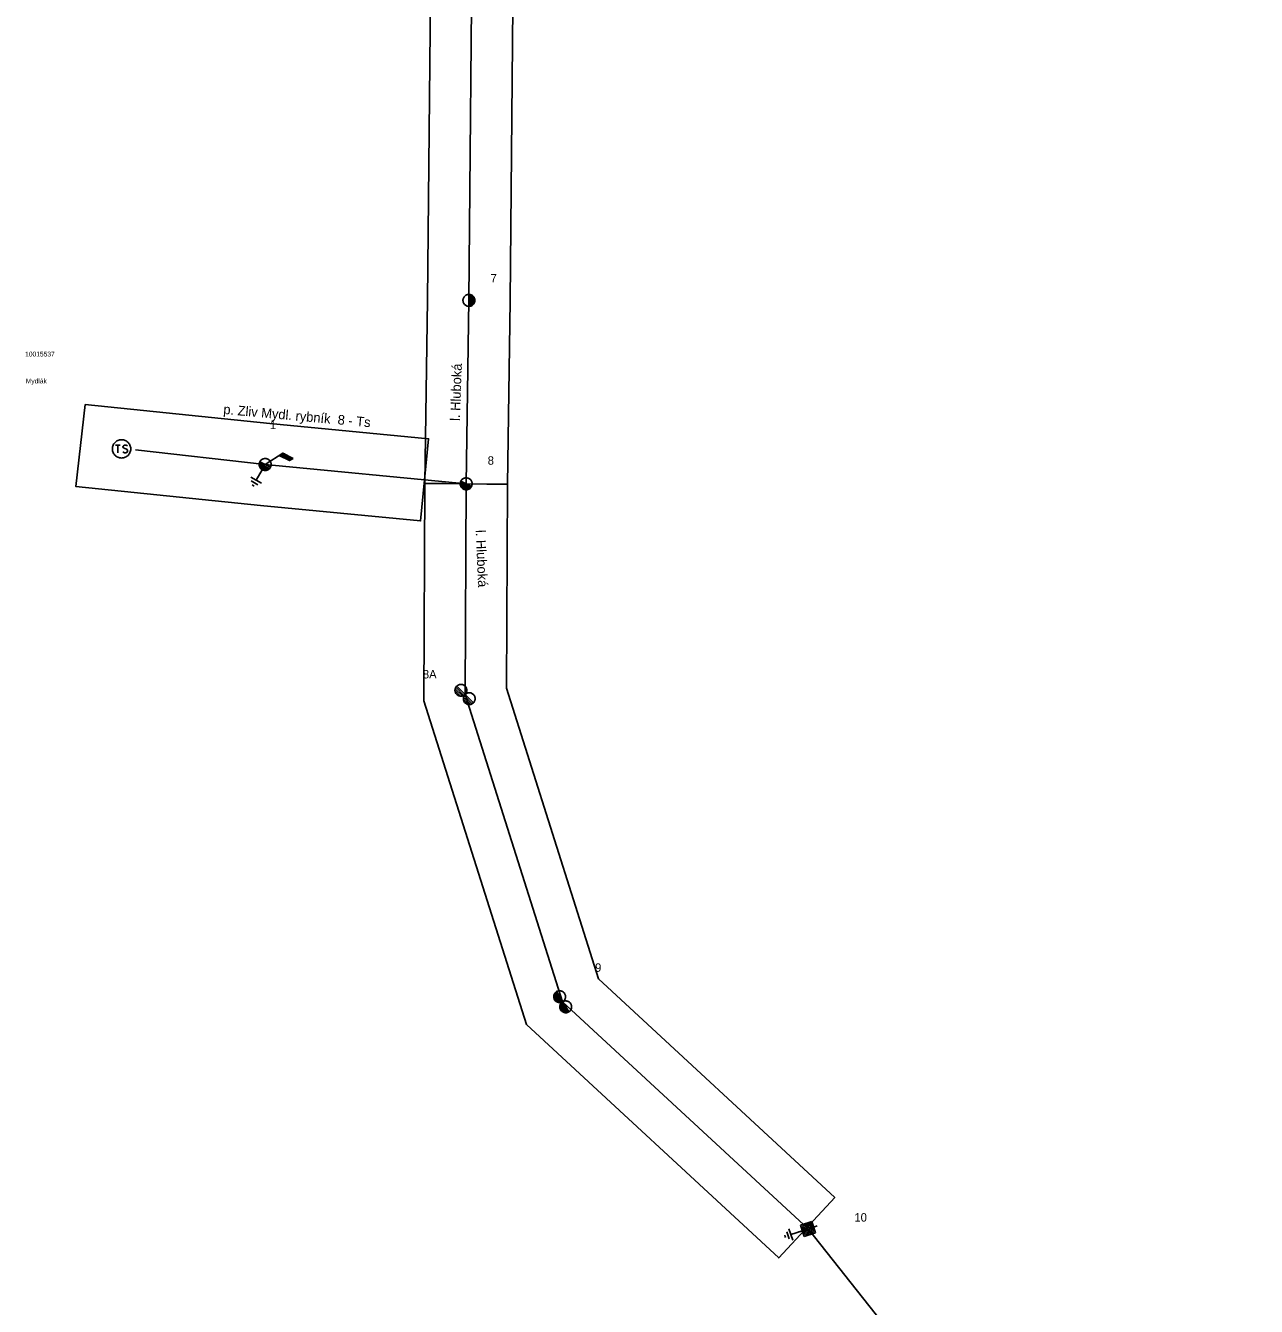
# Model space of a CAD drawing. Extents: x -762349 to -761250, y -1154000 to -1153000.
# Drawn here: x -762349.2 to -762095.6, y -1153527.9 to -1153263.9 of the extents above; entities that cross this region are included whole.
import ezdxf

# ---------------------------------------------------------------- set-up
doc = ezdxf.new("R2010")
doc.units = 0
for name, color, linetype in [('Vrstva 1', 7, 'Continuous'), ('Vrstva 11', 7, 'Continuous'), ('Vrstva 13', 7, 'Continuous'), ('Vrstva 14', 7, 'Continuous'), ('Vrstva 15', 7, 'Continuous'), ('Vrstva 25', 7, 'Continuous'), ('Vrstva 26', 7, 'Continuous'), ('Vrstva 27', 7, 'Continuous'), ('Vrstva 3', 7, 'Continuous'), ('Vrstva 35', 7, 'Continuous'), ('Vrstva 4', 7, 'Continuous'), ('Vrstva 59', 7, 'Continuous')]:
    doc.layers.add(name, color=color, linetype=linetype)

msp = doc.modelspace()

# ---------------------------------------------------------------- linework, layer by layer
at = {"layer": 'Vrstva 1'}
for points in [[(-762255.21, -1153000), (-762255.83, -1153074.97), (-762256.42, -1153159.25), (-762257.11, -1153237.05), (-762257.87, -1153320.54), (-762258.42, -1153358.35)], [(-762258.42, -1153358.35), (-762258.66, -1153401.76), (-762238.55, -1153465.08), (-762187.96, -1153511.89), (-761943.79, -1153820.37), (-761912.01, -1153881.81), (-761868.44, -1153954.91), (-761841.93, -1154000)]]:
    msp.add_lwpolyline(points, dxfattribs=at)
at = {"layer": 'Vrstva 11'}
for p, q in [((-762296.921, -1153352.455), (-762294.771, -1153353.55)), ((-762296.872, -1153352.424), (-762294.723, -1153353.519)), ((-762296.824, -1153352.392), (-762294.675, -1153353.487)), ((-762296.776, -1153352.36), (-762294.626, -1153353.456)), ((-762296.728, -1153352.329), (-762294.578, -1153353.424)), ((-762296.68, -1153352.297), (-762294.529, -1153353.393)), ((-762296.632, -1153352.266), (-762294.481, -1153353.361)), ((-762296.583, -1153352.234), (-762294.432, -1153353.33)), ((-762296.535, -1153352.202), (-762294.384, -1153353.299)), ((-762296.487, -1153352.171), (-762294.336, -1153353.267)), ((-762296.439, -1153352.139), (-762294.287, -1153353.236)), ((-762296.391, -1153352.108), (-762294.239, -1153353.204)), ((-762296.343, -1153352.076), (-762294.19, -1153353.173)), ((-762296.295, -1153352.045), (-762294.142, -1153353.141)), ((-762296.246, -1153352.013), (-762295.88, -1153352.2))]:
    msp.add_line(p, q, dxfattribs=at)
msp.add_lwpolyline([(-762296.246, -1153352.012), (-762299.84, -1153354.37)], dxfattribs=at)
msp.add_lwpolyline([(-762294.097, -1153353.112), (-762296.246, -1153352.012), (-762296.966, -1153352.485), (-762294.816, -1153353.579)], close=True, dxfattribs=at)
at = {"layer": 'Vrstva 13'}
for points in [[(-762257.888, -1153319.321), (-762258.016, -1153319.329), (-762258.142, -1153319.352), (-762258.266, -1153319.387), (-762258.385, -1153319.435), (-762258.499, -1153319.495), (-762258.605, -1153319.568), (-762258.704, -1153319.65), (-762258.793, -1153319.742), (-762258.872, -1153319.844), (-762258.941, -1153319.953), (-762258.997, -1153320.068), (-762259.041, -1153320.189), (-762259.072, -1153320.314), (-762259.09, -1153320.441), (-762259.094, -1153320.57), (-762259.085, -1153320.698), (-762259.063, -1153320.825), (-762259.027, -1153320.949), (-762258.98, -1153321.067), (-762258.919, -1153321.181), (-762258.847, -1153321.288), (-762258.764, -1153321.386), (-762258.672, -1153321.476), (-762258.57, -1153321.555), (-762258.462, -1153321.623), (-762258.346, -1153321.679), (-762258.225, -1153321.723), (-762258.1, -1153321.754), (-762257.973, -1153321.772), (-762257.845, -1153321.777), (-762257.716, -1153321.768), (-762257.59, -1153321.745), (-762257.466, -1153321.71), (-762257.347, -1153321.661), (-762257.233, -1153321.601), (-762257.127, -1153321.53), (-762257.028, -1153321.447), (-762256.939, -1153321.354), (-762256.86, -1153321.253), (-762256.791, -1153321.144), (-762256.735, -1153321.028), (-762256.691, -1153320.908), (-762256.66, -1153320.783), (-762256.642, -1153320.655), (-762256.638, -1153320.527), (-762256.647, -1153320.399), (-762256.669, -1153320.272), (-762256.705, -1153320.149), (-762256.753, -1153320.029), (-762256.813, -1153319.916), (-762256.885, -1153319.809), (-762256.968, -1153319.71), (-762257.06, -1153319.622), (-762257.162, -1153319.542), (-762257.271, -1153319.474), (-762257.386, -1153319.418), (-762257.507, -1153319.374), (-762257.632, -1153319.343), (-762257.759, -1153319.325), (-762257.888, -1153319.321)], [(-762257.852, -1153321.78), (-762257.895, -1153319.324)], [(-762257.508, -1153321.717), (-762257.548, -1153319.433)], [(-762257.223, -1153321.539), (-762257.258, -1153319.562)], [(-762256.94, -1153321.265), (-762256.965, -1153319.845)], [(-762298.755, -1153354.926), (-762298.702, -1153354.809), (-762298.663, -1153354.687), (-762298.636, -1153354.561), (-762298.622, -1153354.433), (-762298.622, -1153354.304), (-762298.636, -1153354.177), (-762298.663, -1153354.051), (-762298.702, -1153353.929), (-762298.754, -1153353.811), (-762298.819, -1153353.699), (-762298.894, -1153353.595), (-762298.981, -1153353.5), (-762299.076, -1153353.414), (-762299.18, -1153353.338), (-762299.292, -1153353.274), (-762299.409, -1153353.222), (-762299.531, -1153353.182), (-762299.657, -1153353.155), (-762299.785, -1153353.142), (-762299.913, -1153353.142), (-762300.041, -1153353.155), (-762300.167, -1153353.182), (-762300.289, -1153353.222), (-762300.407, -1153353.274), (-762300.518, -1153353.339), (-762300.622, -1153353.414), (-762300.718, -1153353.5), (-762300.804, -1153353.596), (-762300.879, -1153353.699), (-762300.944, -1153353.811), (-762300.996, -1153353.928), (-762301.036, -1153354.051), (-762301.062, -1153354.176), (-762301.076, -1153354.305), (-762301.076, -1153354.433), (-762301.062, -1153354.561), (-762301.036, -1153354.686), (-762300.996, -1153354.809), (-762300.944, -1153354.926), (-762300.879, -1153355.038), (-762300.804, -1153355.142), (-762300.718, -1153355.237), (-762300.622, -1153355.323), (-762300.518, -1153355.399), (-762300.407, -1153355.463), (-762300.289, -1153355.515), (-762300.167, -1153355.555), (-762300.041, -1153355.582), (-762299.913, -1153355.595), (-762299.785, -1153355.595), (-762299.657, -1153355.582), (-762299.531, -1153355.555), (-762299.409, -1153355.515), (-762299.291, -1153355.463), (-762299.18, -1153355.399), (-762299.076, -1153355.323), (-762298.981, -1153355.237), (-762298.895, -1153355.141), (-762298.819, -1153355.038), (-762298.755, -1153354.926)], [(-762301.049, -1153354.136), (-762299.013, -1153355.173)], [(-762301.026, -1153354.471), (-762299.264, -1153355.369)], [(-762300.943, -1153353.802), (-762298.754, -1153354.918)], [(-762300.917, -1153354.85), (-762299.651, -1153355.494)], [(-762257.325, -1153358.887), (-762257.275, -1153358.769), (-762257.237, -1153358.646), (-762257.213, -1153358.52), (-762257.201, -1153358.391), (-762257.204, -1153358.263), (-762257.22, -1153358.136), (-762257.248, -1153358.01), (-762257.29, -1153357.889), (-762257.344, -1153357.772), (-762257.411, -1153357.662), (-762257.488, -1153357.559), (-762257.576, -1153357.465), (-762257.673, -1153357.381), (-762257.778, -1153357.307), (-762257.891, -1153357.245), (-762258.009, -1153357.195), (-762258.132, -1153357.157), (-762258.258, -1153357.132), (-762258.386, -1153357.121), (-762258.515, -1153357.123), (-762258.642, -1153357.139), (-762258.768, -1153357.168), (-762258.889, -1153357.21), (-762259.006, -1153357.264), (-762259.116, -1153357.331), (-762259.218, -1153357.408), (-762259.313, -1153357.495), (-762259.397, -1153357.593), (-762259.471, -1153357.698), (-762259.533, -1153357.81), (-762259.584, -1153357.929), (-762259.621, -1153358.051), (-762259.646, -1153358.178), (-762259.657, -1153358.306), (-762259.654, -1153358.435), (-762259.639, -1153358.562), (-762259.61, -1153358.687), (-762259.568, -1153358.809), (-762259.514, -1153358.926), (-762259.448, -1153359.036), (-762259.37, -1153359.139), (-762259.283, -1153359.232), (-762259.185, -1153359.317), (-762259.08, -1153359.391), (-762258.968, -1153359.453), (-762258.849, -1153359.503), (-762258.726, -1153359.541), (-762258.6, -1153359.565), (-762258.472, -1153359.577), (-762258.344, -1153359.574), (-762258.216, -1153359.559), (-762258.09, -1153359.53), (-762257.969, -1153359.488), (-762257.852, -1153359.433), (-762257.742, -1153359.367), (-762257.64, -1153359.29), (-762257.546, -1153359.202), (-762257.461, -1153359.105), (-762257.387, -1153359), (-762257.325, -1153358.887)], [(-762259.632, -1153358.137), (-762257.58, -1153359.139)], [(-762259.533, -1153357.802), (-762257.325, -1153358.879)], [(-762259.604, -1153358.472), (-762257.827, -1153359.338)], [(-762259.488, -1153358.849), (-762258.212, -1153359.471)], [(-762258.659, -1153401.76), (-762258.574, -1153401.665), (-762258.499, -1153401.562), (-762258.436, -1153401.452), (-762258.384, -1153401.335), (-762258.344, -1153401.214), (-762258.318, -1153401.089), (-762258.305, -1153400.962), (-762258.305, -1153400.835), (-762258.318, -1153400.708), (-762258.344, -1153400.583), (-762258.384, -1153400.462), (-762258.436, -1153400.345), (-762258.499, -1153400.234), (-762258.574, -1153400.132), (-762258.66, -1153400.037), (-762258.755, -1153399.951), (-762258.857, -1153399.876), (-762258.968, -1153399.813), (-762259.085, -1153399.761), (-762259.206, -1153399.721), (-762259.331, -1153399.695), (-762259.458, -1153399.681), (-762259.585, -1153399.681), (-762259.712, -1153399.695), (-762259.837, -1153399.721), (-762259.958, -1153399.761), (-762260.075, -1153399.813), (-762260.185, -1153399.876), (-762260.288, -1153399.951), (-762260.383, -1153400.037), (-762260.469, -1153400.132), (-762260.544, -1153400.234), (-762260.607, -1153400.345), (-762260.659, -1153400.462), (-762260.699, -1153400.583), (-762260.725, -1153400.708), (-762260.738, -1153400.835), (-762260.738, -1153400.962), (-762260.725, -1153401.089), (-762260.698, -1153401.214), (-762260.659, -1153401.335), (-762260.607, -1153401.452), (-762260.544, -1153401.562), (-762260.469, -1153401.665), (-762260.383, -1153401.76), (-762260.288, -1153401.846), (-762260.185, -1153401.92), (-762260.075, -1153401.984), (-762259.958, -1153402.036), (-762259.837, -1153402.076), (-762259.712, -1153402.102), (-762259.585, -1153402.115), (-762259.458, -1153402.115), (-762259.331, -1153402.102), (-762259.206, -1153402.075), (-762259.085, -1153402.036), (-762258.968, -1153401.984), (-762258.857, -1153401.92), (-762258.755, -1153401.846), (-762258.66, -1153401.761)], [(-762260.573, -1153400.281), (-762258.904, -1153401.95)], [(-762260.383, -1153400.037), (-762256.936, -1153403.484)], [(-762260.735, -1153400.987), (-762259.609, -1153402.113)], [(-762260.695, -1153400.593), (-762259.216, -1153402.072)], [(-762256.936, -1153403.484), (-762256.851, -1153403.389), (-762256.776, -1153403.286), (-762256.712, -1153403.175), (-762256.66, -1153403.059), (-762256.62, -1153402.937), (-762256.594, -1153402.813), (-762256.581, -1153402.685), (-762256.581, -1153402.558), (-762256.594, -1153402.431), (-762256.621, -1153402.306), (-762256.66, -1153402.185), (-762256.712, -1153402.069), (-762256.776, -1153401.958), (-762256.851, -1153401.855), (-762256.937, -1153401.76), (-762257.031, -1153401.675), (-762257.134, -1153401.6), (-762257.245, -1153401.536), (-762257.362, -1153401.484), (-762257.483, -1153401.445), (-762257.607, -1153401.418), (-762257.734, -1153401.405), (-762257.861, -1153401.405), (-762257.988, -1153401.418), (-762258.113, -1153401.445), (-762258.235, -1153401.485), (-762258.351, -1153401.536), (-762258.462, -1153401.6), (-762258.565, -1153401.675), (-762258.66, -1153401.761), (-762258.745, -1153401.855), (-762258.82, -1153401.958), (-762258.884, -1153402.069), (-762258.936, -1153402.186), (-762258.975, -1153402.307), (-762259.001, -1153402.431), (-762259.015, -1153402.558), (-762259.015, -1153402.685), (-762259.001, -1153402.813), (-762258.975, -1153402.938), (-762258.935, -1153403.059), (-762258.884, -1153403.175), (-762258.82, -1153403.286), (-762258.745, -1153403.389), (-762258.659, -1153403.484), (-762258.565, -1153403.569), (-762258.462, -1153403.644), (-762258.351, -1153403.708), (-762258.234, -1153403.76), (-762258.113, -1153403.799), (-762257.988, -1153403.825), (-762257.861, -1153403.839), (-762257.734, -1153403.839), (-762257.607, -1153403.825), (-762257.482, -1153403.799), (-762257.361, -1153403.759), (-762257.245, -1153403.708), (-762257.134, -1153403.644), (-762257.031, -1153403.569), (-762256.936, -1153403.484)], [(-762259.012, -1153402.71), (-762257.886, -1153403.836)], [(-762258.971, -1153402.316), (-762257.492, -1153403.796)], [(-762258.849, -1153402.005), (-762257.18, -1153403.673)], [(-762238.55, -1153465.08), (-762238.444, -1153465.008), (-762238.347, -1153464.927), (-762238.258, -1153464.835), (-762238.18, -1153464.734), (-762238.112, -1153464.626), (-762238.056, -1153464.512), (-762238.012, -1153464.391), (-762237.982, -1153464.268), (-762237.964, -1153464.142), (-762237.959, -1153464.014), (-762237.969, -1153463.887), (-762237.991, -1153463.761), (-762238.025, -1153463.638), (-762238.073, -1153463.521), (-762238.134, -1153463.408), (-762238.205, -1153463.302), (-762238.286, -1153463.204), (-762238.378, -1153463.116), (-762238.479, -1153463.037), (-762238.587, -1153462.969), (-762238.702, -1153462.914), (-762238.822, -1153462.87), (-762238.945, -1153462.839), (-762239.072, -1153462.822), (-762239.199, -1153462.817), (-762239.326, -1153462.826), (-762239.452, -1153462.848), (-762239.575, -1153462.883), (-762239.693, -1153462.931), (-762239.806, -1153462.991), (-762239.911, -1153463.062), (-762240.009, -1153463.144), (-762240.097, -1153463.236), (-762240.176, -1153463.337), (-762240.244, -1153463.445), (-762240.299, -1153463.559), (-762240.343, -1153463.679), (-762240.374, -1153463.803), (-762240.392, -1153463.929), (-762240.396, -1153464.057), (-762240.387, -1153464.184), (-762240.365, -1153464.31), (-762240.33, -1153464.432), (-762240.282, -1153464.55), (-762240.222, -1153464.663), (-762240.151, -1153464.769), (-762240.069, -1153464.867), (-762239.977, -1153464.955), (-762239.877, -1153465.034), (-762239.768, -1153465.102), (-762239.654, -1153465.157), (-762239.534, -1153465.201), (-762239.411, -1153465.232), (-762239.284, -1153465.249), (-762239.156, -1153465.254), (-762239.029, -1153465.245), (-762238.904, -1153465.223), (-762238.781, -1153465.188), (-762238.663, -1153465.14), (-762238.55, -1153465.081)], [(-762240.377, -1153463.827), (-762239.557, -1153465.192)], [(-762240.243, -1153463.455), (-762239.165, -1153465.249)], [(-762240.048, -1153463.182), (-762238.833, -1153465.205)], [(-762239.805, -1153462.991), (-762237.294, -1153467.17)], [(-762237.294, -1153467.17), (-762237.189, -1153467.098), (-762237.091, -1153467.016), (-762237.003, -1153466.924), (-762236.924, -1153466.824), (-762236.856, -1153466.715), (-762236.801, -1153466.601), (-762236.757, -1153466.481), (-762236.726, -1153466.358), (-762236.709, -1153466.231), (-762236.704, -1153466.103), (-762236.713, -1153465.976), (-762236.735, -1153465.851), (-762236.77, -1153465.728), (-762236.818, -1153465.61), (-762236.878, -1153465.497), (-762236.949, -1153465.391), (-762237.031, -1153465.294), (-762237.123, -1153465.205), (-762237.224, -1153465.126), (-762237.332, -1153465.059), (-762237.446, -1153465.003), (-762237.566, -1153464.959), (-762237.69, -1153464.929), (-762237.816, -1153464.911), (-762237.944, -1153464.906), (-762238.071, -1153464.915), (-762238.197, -1153464.938), (-762238.319, -1153464.972), (-762238.437, -1153465.02), (-762238.55, -1153465.081), (-762238.656, -1153465.152), (-762238.754, -1153465.233), (-762238.842, -1153465.325), (-762238.921, -1153465.426), (-762238.989, -1153465.534), (-762239.044, -1153465.649), (-762239.088, -1153465.769), (-762239.119, -1153465.892), (-762239.136, -1153466.019), (-762239.141, -1153466.146), (-762239.132, -1153466.273), (-762239.11, -1153466.399), (-762239.075, -1153466.522), (-762239.027, -1153466.64), (-762238.967, -1153466.753), (-762238.895, -1153466.858), (-762238.814, -1153466.956), (-762238.722, -1153467.044), (-762238.621, -1153467.123), (-762238.513, -1153467.191), (-762238.399, -1153467.246), (-762238.278, -1153467.29), (-762238.155, -1153467.321), (-762238.029, -1153467.339), (-762237.901, -1153467.343), (-762237.774, -1153467.334), (-762237.648, -1153467.312), (-762237.525, -1153467.277), (-762237.408, -1153467.229), (-762237.295, -1153467.17)], [(-762239.122, -1153465.917), (-762238.302, -1153467.282)], [(-762238.987, -1153465.544), (-762237.91, -1153467.338)], [(-762238.793, -1153465.272), (-762237.577, -1153467.295)], [(-762189.512, -1153511.103), (-762187.175, -1153510.344)], [(-762188.753, -1153513.439), (-762189.512, -1153511.103)], [(-762189.143, -1153511.306), (-762187.391, -1153510.737)], [(-762188.574, -1153513.058), (-762189.143, -1153511.306)], [(-762188.738, -1153511.497), (-762187.569, -1153511.117)], [(-762187.569, -1153511.117), (-762187.19, -1153512.286)], [(-762187.391, -1153510.737), (-762186.822, -1153512.489)], [(-762187.175, -1153510.344), (-762186.416, -1153512.68)], [(-762186.796, -1153511.512), (-762186.084, -1153511.281)], [(-762189.132, -1153512.271), (-762189.844, -1153512.502)], [(-762186.416, -1153512.68), (-762188.753, -1153513.439)], [(-762188.359, -1153512.665), (-762188.738, -1153511.497)], [(-762186.822, -1153512.489), (-762188.574, -1153513.058)], [(-762187.19, -1153512.286), (-762188.359, -1153512.665)], [(-762188.314, -1153511.682), (-762187.73, -1153511.493)], [(-762188.125, -1153512.266), (-762188.314, -1153511.682)], [(-762187.541, -1153512.077), (-762188.125, -1153512.266)], [(-762187.73, -1153511.493), (-762187.541, -1153512.077)]]:
    msp.add_lwpolyline(points, dxfattribs=at)
at = {"layer": 'Vrstva 15'}
for points in [[(-762300.461, -1153355.452), (-762301.711, -1153357.617)], [(-762300.628, -1153358.242), (-762302.793, -1153356.992)], [(-762301.356, -1153358.538), (-762302.72, -1153357.751)], [(-762302.336, -1153358.7), (-762302.558, -1153358.572)], [(-762302.106, -1153358.833), (-762302.336, -1153358.7)], [(-762192.711, -1153513.437), (-762192.79, -1153513.194)], [(-762192.629, -1153513.69), (-762192.711, -1153513.437)], [(-762191.875, -1153513.973), (-762192.362, -1153512.475)], [(-762191.136, -1153514.24), (-762191.909, -1153511.862)], [(-762189.145, -1153512.278), (-762191.522, -1153513.051)]]:
    msp.add_lwpolyline(points, dxfattribs=at)
at = {"layer": 'Vrstva 25'}
for points in [[(-762327.567, -1153351.151), (-762327.578, -1153350.954), (-762327.609, -1153350.758), (-762327.66, -1153350.567), (-762327.732, -1153350.382), (-762327.821, -1153350.207), (-762327.929, -1153350.041), (-762328.053, -1153349.887), (-762328.193, -1153349.747), (-762328.347, -1153349.623), (-762328.513, -1153349.515), (-762328.689, -1153349.425), (-762328.873, -1153349.354), (-762329.065, -1153349.303), (-762329.26, -1153349.272), (-762329.457, -1153349.261), (-762329.655, -1153349.272), (-762329.851, -1153349.303), (-762330.041, -1153349.354), (-762330.227, -1153349.425), (-762330.402, -1153349.515), (-762330.568, -1153349.623), (-762330.722, -1153349.747), (-762330.862, -1153349.887), (-762330.986, -1153350.041), (-762331.094, -1153350.207), (-762331.184, -1153350.382), (-762331.255, -1153350.567), (-762331.306, -1153350.758), (-762331.337, -1153350.954), (-762331.348, -1153351.151), (-762331.337, -1153351.349), (-762331.306, -1153351.545), (-762331.255, -1153351.735), (-762331.184, -1153351.92), (-762331.094, -1153352.096), (-762330.986, -1153352.262), (-762330.861, -1153352.416), (-762330.722, -1153352.555), (-762330.568, -1153352.68), (-762330.402, -1153352.788), (-762330.226, -1153352.878), (-762330.041, -1153352.949), (-762329.851, -1153353), (-762329.655, -1153353.031), (-762329.457, -1153353.042), (-762329.26, -1153353.031), (-762329.065, -1153353), (-762328.873, -1153352.949), (-762328.689, -1153352.878), (-762328.513, -1153352.788), (-762328.347, -1153352.68), (-762328.193, -1153352.555), (-762328.053, -1153352.416), (-762327.929, -1153352.262), (-762327.821, -1153352.096), (-762327.732, -1153351.92), (-762327.66, -1153351.735), (-762327.609, -1153351.545), (-762327.578, -1153351.349), (-762327.567, -1153351.151)], [(-762330.719, -1153350.368), (-762329.711, -1153350.368)], [(-762330.215, -1153350.368), (-762330.215, -1153351.942)], [(-762328.262, -1153350.494), (-762328.514, -1153350.368), (-762328.829, -1153350.368), (-762329.081, -1153350.494), (-762329.207, -1153350.682), (-762329.207, -1153350.746), (-762329.081, -1153350.934), (-762328.325, -1153351.312), (-762328.199, -1153351.47), (-762328.199, -1153351.628), (-762328.325, -1153351.816), (-762328.577, -1153351.942), (-762328.829, -1153351.942), (-762328.955, -1153351.88), (-762329.207, -1153351.754)]]:
    msp.add_lwpolyline(points, dxfattribs=at)
at = {"layer": 'Vrstva 35'}
msp.add_lwpolyline([(-762263.71, -1153000), (-762264.33, -1153074.91), (-762264.92, -1153159.18), (-762265.61, -1153236.97), (-762266.37, -1153320.44), (-762266.92, -1153358.23), (-762249.92, -1153358.47), (-762249.37, -1153320.64), (-762248.61, -1153237.13), (-762247.92, -1153159.32), (-762247.33, -1153075.03), (-762246.71, -1153000)], dxfattribs=at)
for points in [[(-762336.97, -1153342.03), (-762338.87, -1153358.92), (-762300.79, -1153362.82), (-762267.82, -1153365.99), (-762266.19, -1153349.06), (-762298.89, -1153345.92)], [(-762249.92, -1153358.4), (-762266.92, -1153358.3), (-762267.17, -1153403.05), (-762245.97, -1153469.79), (-762194.02, -1153517.86), (-762182.47, -1153505.39), (-762231.13, -1153460.37), (-762250.15, -1153400.47)]]:
    msp.add_lwpolyline(points, close=True, dxfattribs=at)
at = {"layer": 'Vrstva 4'}
for points in [[(-762299.84, -1153354.37), (-762326.57, -1153351.37)], [(-762258.42, -1153358.35), (-762299.84, -1153354.37)]]:
    msp.add_lwpolyline(points, dxfattribs=at)

# ---------------------------------------------------------------- texts
at = {"layer": 'Vrstva 14'}
for s, p in [('7', (-762253.41, -1153316.85)), ('1', (-762298.9, -1153347.09)), ('8', (-762254, -1153354.42)), ('8A', (-762267.37, -1153398.46)), ('9', (-762231.87, -1153458.91)), ('10', (-762178.43, -1153510.39))]:
    msp.add_text(s, height=1.74, dxfattribs=at).set_placement(p)
at = {"layer": 'Vrstva 26'}
msp.add_text('10015537', height=0.9943, dxfattribs=at).set_placement((-762349.33, -1153332.11))
at = {"layer": 'Vrstva 27'}
msp.add_text('Mydlák', height=0.9943, dxfattribs=at).set_placement((-762349.2, -1153337.66))
at = {"layer": 'Vrstva 3'}
for rotation, p in [(87.88939, (-762259.75, -1153345.42)), (272.50027, (-762256.48, -1153367.89))]:
    msp.add_text('l. Hluboká', height=1.9886, rotation=rotation, dxfattribs=at).set_placement(p)
at = {"layer": 'Vrstva 59'}
msp.add_text('p. Zliv Mydl. rybník  8 - Ts', height=1.98858, rotation=354.82704, dxfattribs=at).set_placement((-762308.54, -1153343.95))

doc.saveas('drawing.dxf')
